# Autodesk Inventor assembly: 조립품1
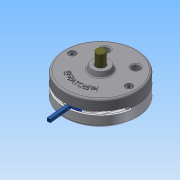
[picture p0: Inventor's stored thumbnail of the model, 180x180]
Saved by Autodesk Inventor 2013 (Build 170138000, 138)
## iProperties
Created: 2015-06
Part Number: 조립품1
Document SubType Name: Assembly
Designer: Administrator
Author: Administrator
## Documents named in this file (10)
- C:\Documents and Settings\Administrator\바탕 화면\450631V1013\조립품1.iam
- C:\Documents and Settings\Administrator\바탕 화면\450631V1013\본체.ipt
- C:\Documents and Settings\Administrator\바탕 화면\450631V1013\덮개.ipt
- C:\Documents and Settings\Administrator\바탕 화면\450631V1013\멈춤링.ipt
- C:\Documents and Settings\Administrator\바탕 화면\450631V1013\베어링62_22.ipt
- C:\Documents and Settings\Administrator\바탕 화면\450631V1013\슬라이더.ipt
- C:\Documents and Settings\Administrator\바탕 화면\450631V1013\슬라이더2.ipt
- C:\Documents and Settings\Administrator\바탕 화면\450631V1013\축.ipt
- C:\Documents and Settings\Administrator\바탕 화면\450631V1013\평행핀.ipt
- C:\Documents and Settings\Administrator\바탕 화면\450631V1013\M10x35.ipt
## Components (7 placed, 4 different names)
1. KS B 1336 22 x 1.2:1
2. KS B 2023 62/22 - 22 x 50 x 14:1
3. KS B 1320 B B 5 x  20:1 — 플러쉬:1
4. KS B 1003 - 미터 M 10 x 35:1
5. KS B 1003 - 미터 M 10 x 35:2
6. KS B 2023 62/22 - 22 x 50 x 14:2
7. KS B 1336 22 x 1.2:2
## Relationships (1: Flush 1)
- 플러쉬:1 [Flush]: KS B 1320 B B 5 x  20:1
